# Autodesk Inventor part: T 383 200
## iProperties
Company: Mayer & Mueller Schaltgeräte AG
Created: 2006-07
Part Number: T 383 200
Material: 1.0110
Description: Schalthebel
Document SubType Name: Modeling
Designer: I.Baliuc
Manufacturer: Standard
Standards Organization: Custom
Density: 7.85 g/cm^3
Author: T.Messerschmitt
Revision Number: 383200
Comments: Für die Vorkontaktseite
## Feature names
1. Extrusion4
2. Bezeichnung2 [Tagging]
